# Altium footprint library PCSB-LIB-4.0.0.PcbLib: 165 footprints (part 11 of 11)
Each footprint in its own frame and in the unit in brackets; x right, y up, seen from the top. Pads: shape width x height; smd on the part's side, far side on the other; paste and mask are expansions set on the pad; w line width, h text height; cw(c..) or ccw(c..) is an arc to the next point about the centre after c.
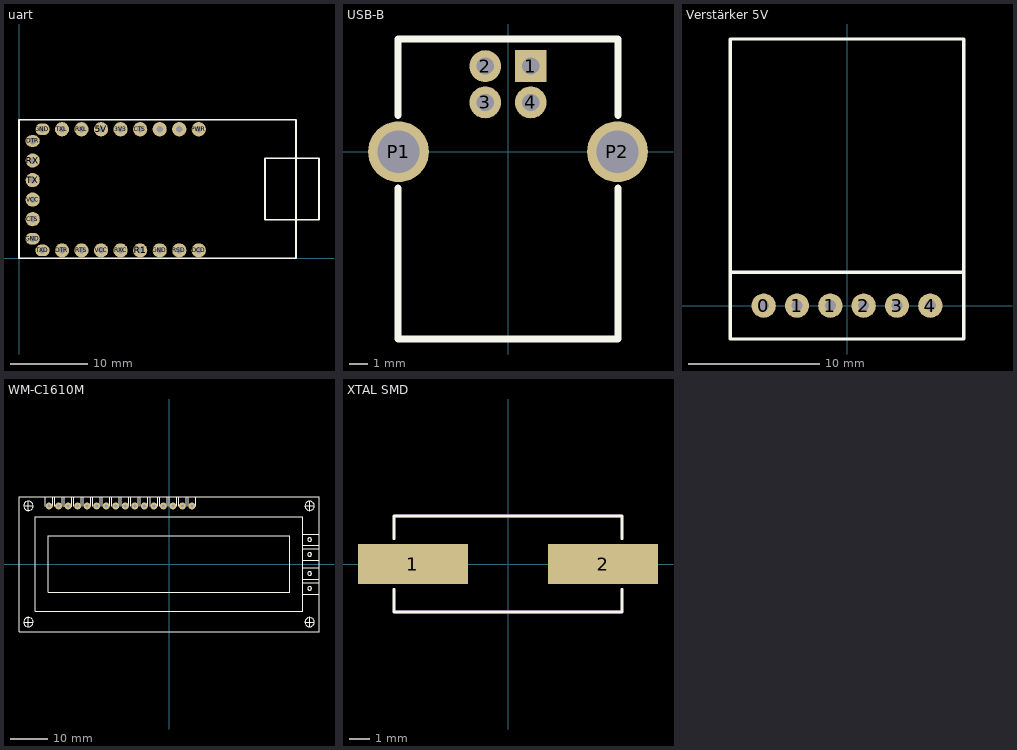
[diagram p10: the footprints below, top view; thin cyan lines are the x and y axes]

## uart [mm]
pads (24):
  round 1.85 hole 0.85: 3V3(13.208,16.764) 5V(10.668,16.764) CTS(1.778,5.08) CTS(15.748,16.764) DCD(23.368,1.016) DTR(5.588,1.016) ENTEN(20.828,16.764) GND(18.288,1.016) PWR(23.368,16.764) R1(15.748,1.016) RSD(20.828,1.016) RTS(8.128,1.016) RX(1.778,12.7) RXC(13.208,1.016) RXL(8.128,16.764) SLEEP(18.288,16.764) TX(1.778,10.16) TXL(5.588,16.764) VCC(1.778,7.62) VCC(10.668,1.016)
  oval 1.85x1.5 hole 0.85: DTR(1.778,15.24) GND(1.778,2.54) GND(3.048,16.764) TXD(3.048,1.016)
Top Overlay:
  lines w0.254: 0,0 0,18 36,18 36,0 0,0 ; 32,5 39,5 39,13 34,13 32,13 32,5

## USB-B [mm]
pads (6):
  rect 1.75x1.75 hole 0.95: 1(1.25,4.71)
  round 1.75 hole 0.95: 2(-1.25,4.71) 3(-1.25,2.71) 4(1.25,2.71)
  round 3.346 hole 2.33: P1(-6.02,0) P2(6.02,0)
Top Overlay:
  lines w0.4: -6.05,-2 -6.05,-10.3 6.05,-10.3 6.05,-2 ; -6.05,2 -6.05,6.2 6.05,6.2 6.05,2

## Verstärker 5V [mm]
pads (6):
  round 1.85 hole 0.85: 0(-6.35,0) 1(-3.81,0) 1(-1.27,0) 2(1.27,0) 3(3.81,0) 4(6.35,0)
Top Overlay:
  lines w0.254: -8.89,2.54 8.89,2.54 ; -8.89,-2.54 -8.89,0 -8.89,20.32 8.89,20.32 8.89,-2.54 -8.89,-2.54

## WM-C1610M [mm]
pads (16):
  round 1.85 hole 0.85: 1(-32,15.5) 2(-29.46,15.5) 3(-26.92,15.5) 4(-24.38,15.5) 5(-21.84,15.5) 6(-19.3,15.5) 7(-16.76,15.5) 8(-14.22,15.5) 9(-11.68,15.5) 10(-9.14,15.5) 11(-6.6,15.5) 12(-4.06,15.5) 13(-1.52,15.5) 14(1.02,15.5) 15(3.56,15.5) 16(6.1,15.5)
Top Overlay:
  circle w0.2: c-37.51,15.538 r1.25
  circle w0.2: c-37.51,-15.462 r1.25
  circle w0.2: c37.49,15.538 r1.25
  circle w0.2: c37.49,6.538 r0.5
  circle w0.2: c37.49,2.578 r0.5
  circle w0.2: c37.49,-2.502 r0.5
  circle w0.2: c37.49,-6.462 r0.5
  circle w0.2: c37.49,-15.462 r1.25
  lines w0.1: -38.75,-15.462 -36.26,-15.462 ; -38.75,15.538 -36.26,15.538 ; -37.51,-16.75 -37.51,-14.25 ; -37.51,14.25 -37.51,16.75 ; 36.25,-15.462 38.74,-15.462 ; 36.25,15.538 38.74,15.538 ; 37.49,-16.75 37.49,-14.25 ; 37.49,14.25 37.49,16.75
  lines w0.2: -33.01,15.498 -33.01,18.038 ; -31.01,15.498 -31.01,18.038 ; -30.47,15.498 -30.47,18.038 ; -28.47,15.498 -28.47,18.038 ; -27.93,15.338 -27.93,18.038 ; -25.93,15.338 -25.93,18.038 ; -25.39,15.498 -25.39,18.038 ; -23.39,15.498 -23.39,18.038 ; -22.85,15.498 -22.85,18.038 ; -20.85,15.498 -20.85,18.038 ; -20.31,15.498 -20.31,18.038 ; -18.31,15.498 -18.31,18.038 ; -17.77,15.498 -17.77,18.038 ; -15.77,15.498 -15.77,18.038 ; -15.23,15.498 -15.23,18.038 ; -13.23,15.498 -13.23,18.038 ; -12.69,15.498 -12.69,18.038 ; -10.69,15.498 -10.69,18.038 ; -10.15,15.468 -10.15,18.038 ; -8.15,15.468 -8.15,18.038 ; -7.61,15.468 -7.61,18.038 ; -5.61,15.468 -5.61,18.038 ; -5.07,15.498 -5.07,18.038 ; -3.07,15.498 -3.07,18.038 ; -2.53,15.498 -2.53,18.038 ; -0.53,15.498 -0.53,18.038 ; 0.01,15.498 0.01,18.038 ; 2.01,15.498 2.01,18.038 ; 2.55,15.498 2.55,18.038 ; 4.55,15.498 4.55,18.038 ; 5.09,15.498 5.09,18.038 ; 7.09,15.498 7.09,18.038 ; 35.59,-7.962 39.99,-7.962 ; 35.59,-4.962 39.99,-4.962 ; 35.59,-4.002 39.99,-4.002 ; 35.59,-1.002 39.99,-1.002 ; 35.59,1.078 39.99,1.078 ; 35.59,4.078 39.99,4.078 ; 35.59,5.038 39.99,5.038 ; 35.59,8.038 39.99,8.038 ; -40.01,-17.962 39.99,-17.962 39.99,18.038 -40.01,18.038 -40.01,-17.962 ; -35.61,-12.562 -35.61,12.638 35.59,12.638 35.59,-12.562 -35.61,-12.562 ; -32.24,-7.462 32.22,-7.462 32.22,7.538 -32.24,7.538 -32.24,-7.462

## XTAL SMD [mm]
pads (2):
  rect 5.5x2 smd: 1(-4.75,0) 2(4.75,0)
Top Overlay:
  lines w0.127: -5.7,-1.254 -5.7,-2.4 5.7,-2.4 5.7,-1.254 ; -5.7,1.254 -5.7,2.4 5.7,2.4 5.7,1.254
Mechanical 13:
  lines w0.127: -5.7,-2.4 5.7,-2.4 ; -5.7,2.4 5.7,2.4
